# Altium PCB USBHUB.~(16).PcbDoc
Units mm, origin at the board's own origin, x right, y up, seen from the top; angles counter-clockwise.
Board outline 31.37 x 90.68 mm, 2 copper layers (Top Layer, Bottom Layer); 37 components, 26 nets, 182 pads, 0 vias.
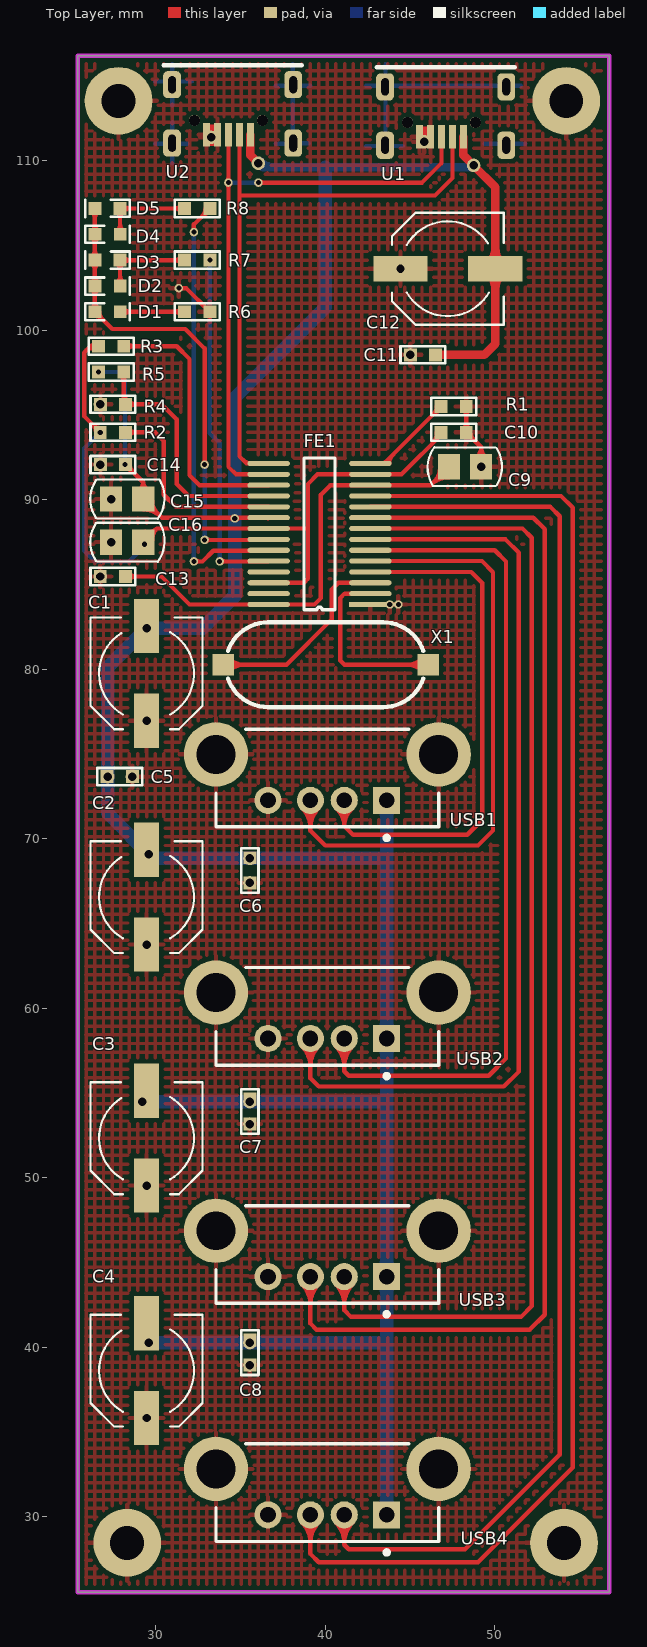
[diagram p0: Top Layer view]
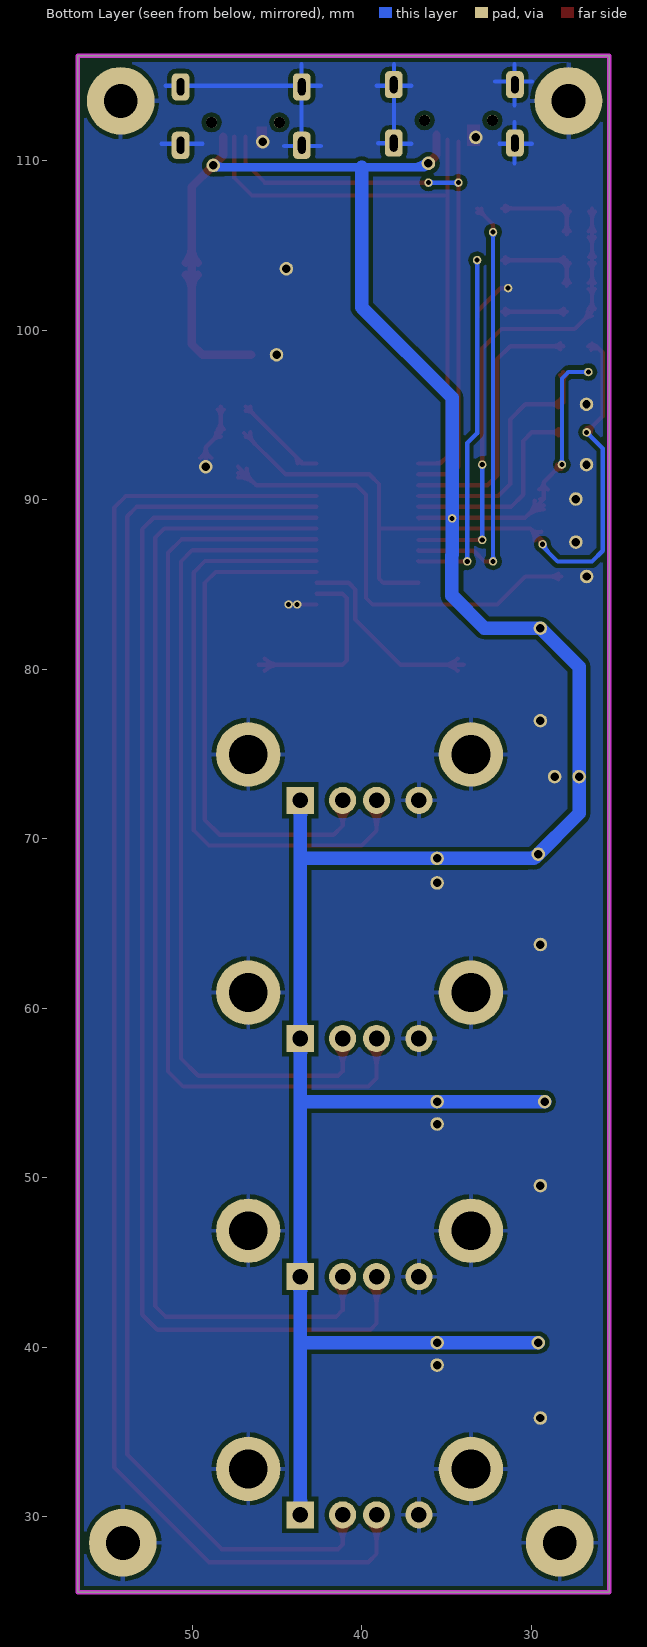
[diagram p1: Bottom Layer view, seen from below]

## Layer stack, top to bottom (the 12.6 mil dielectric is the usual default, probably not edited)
Top Layer: signal copper 0.0356
Dielectric: dielectric 0.32, FR-4, Dk 4.8
Bottom Layer: signal copper 0.0356

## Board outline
25.4,116.205 56.769,116.205 56.769,25.527 25.4,25.527 25.4,116.205

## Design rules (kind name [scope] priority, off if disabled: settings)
Clearance [All] p1: gap=0.254
PolygonConnect [All] p1: connectstyle=Relief reliefconductorwidth=0.254 reliefentries=4 polygonreliefangle="90 Angle"
RoutingVias [All] p1: holewidth=0.711 width=1.27 viastyle="Through Hole" minholewidth=0.711 minwidth=1.27 maxholewidth=0.711 maxwidth=1.27
SilkscreenOverComponentPads [All] p1: minsilkscreentomaskgap=0.254
SolderMaskExpansion [All] p1: expansion=0.102
TestPointUsage [All] p1: valid=0 allowmultiple=FALSE
Testpoint [All] p1: side=15 testpointundercomponent=TRUE minsize=1.016 maxsize=2.54 preferedsize=1.524 minholesize=0 maxholesize=1.016 preferedholesize=0.813 testpointgrid=0.025 style=1023 order=0123456789
Width [All] p1: maxlimit=2 minlimit=0.254 preferedwidth=0.254
23 further rules are at their usual default settings.

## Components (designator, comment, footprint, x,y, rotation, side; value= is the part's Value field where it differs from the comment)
C1 "Cap_Pol" cap_220uF/16V 29.464,79.756 r90 top
C2 "Cap_Pol" cap_220uF/16V 29.464,66.548 r90 top
C3 "Cap_Pol" cap_220uF/16V 29.464,52.324 r90 top
C4 "Cap_Pol" cap_220uF/16V 29.464,38.608 r90 top
C5 "Cap1" 0603 27.94,73.66 r180 top
C6 "Cap1" 0603 35.56,68.072 r90 top
C7 "Cap1" 0603 35.56,53.848 r90 top
C8 "Cap1" 0603 35.56,39.624 r90 top
C9 "Cap1" 2012[0805]-C 48.26,91.948 r180 top
C10 "Cap1" 0603 47.647,93.98 r180 top
C11 "Cap1" 0603 45.72,98.552 r0 top
C12 "Cap_Pol" cap_220uF/16V 47.244,103.632 r0 top
C13 "Cap1" 0603 27.534,85.471 r180 top
C14 "Cap1" 0603 27.429,92.075 r0 top
C15 "Cap1" 2012[0805]-C 28.321,90.043 r0 top
C16 "Cap1" 2012[0805]-C 28.321,87.503 r0 top
D1 "LED" 0603-Polar 27.111,101.092 r0 top
D2 "LED" 0603-Polar 27.111,102.616 r0 top
D3 "LED" 0603-Polar 27.216,104.14 r180 top
D4 "LED" 0603-Polar 27.111,105.664 r0 top
D5 "LED" 0603-Polar 27.216,107.188 r180 top
FE1 "FE1.1s" SSOP-28 42.672,83.82 r180 top
R1 "Res1" 0603 47.647,95.504 r180 top
R2 "Res1" 0603 27.534,93.98 r180 top
R3 "Res1" 0603 27.432,99.06 r180 top
R4 "Res1" 0603 27.429,95.631 r0 top
R5 "Res1" 0603 27.432,97.536 r180 top
R6 "Res1" 0603 32.512,101.092 r180 top
R7 "Res1" 0603 32.512,104.14 r180 top
R8 "Res1" 0603 32.512,107.188 r180 top
U1 "Micro-USB" MICRO-USB-F 47.117,113.665 r180 top
U2 "Micro-USB" MICRO-USB-F 34.544,113.792 r180 top
USB1 "USB" USB2.5-2V4A 40.132,76.454 r90 top
USB2 "USB" USB2.5-2V4A 40.132,62.399 r90 top
USB3 "USB" USB2.5-2V4A 40.132,48.345 r90 top
USB4 "USB" USB2.5-2V4A 40.132,34.29 r90 top
X1 "12M" XTAL_SMD 37.592,80.264 r0 top

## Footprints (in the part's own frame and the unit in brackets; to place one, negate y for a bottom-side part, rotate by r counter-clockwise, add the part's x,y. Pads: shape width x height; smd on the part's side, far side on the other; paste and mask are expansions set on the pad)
0603 [mil]
  rect 30x30 smd: 1(-27,0) 2(31.5,0)
  silkscreen extent -50,-20 54,20
0603-Polar [mil]
  rect 30x30 smd: 1(-27,0) 2(31.5,0)
  silkscreen extent -50,-20 54,20
2012[0805]-C [mm] "Chip Resistor; Body 2.0 x 1.3 mm (LxW typ)"
  rect 1.3x1.5 smd: 1(-0.95,0) 2(0.95,0)
  silkscreen extent -2.17,-1.16 2.21,1.14
cap_220uF/16V [mm]
  rect 3.2x1.5 smd: 1(-2.794,0) 2(2.8,0)
  silkscreen extent -3.3,-3.3 3.3,3.3
MICRO-USB-F [mm]
  rrect50% 1.05x1.6 hole 0.45 slot 1 at 90 deg: 0(-3.575,-0.7) 0(-3.575,2.75) 0(3.575,-0.7) 0(3.575,2.75)
  round 0.65 hole 0.65: 0(-1.75,1.4) 0(2.25,1.4)
  rect 0.4x1.4 smd: 1(-1.05,2.25) 2(-0.403,2.25) 3(0.246,2.25) 4(0.897,2.25) 5(1.546,2.25)
  silkscreen extent -4.08,-1.85 4.08,-1.85
SSOP-28 [mm]
  rect 2.5x0.3 smd: 1(0,0)
  oval 2.5x0.3 smd: 2(0,-0.64) 3(0,-1.28) 4(0,-1.92) 5(0,-2.56) 6(0,-3.2) 7(0,-3.84) 8(0,-4.48) 9(0,-5.12) 10(0,-5.76) 11(0,-6.4) 12(0,-7.04) 13(0,-7.68) 14(0,-8.32) 15(6,-8.32) 16(6,-7.68) 17(6,-7.04) 18(6,-6.4) 19(6,-5.76) 20(6,-5.12) 21(6,-4.48) 22(6,-3.84) 23(6,-3.2) 24(6,-2.56) 25(6,-1.92) 26(6,-1.28) 27(6,-0.64) 28(6,0)
  silkscreen extent 2.08,-8.64 3.92,0.32
USB2.5-2V4A [mm] "Connector; USB1.1, Type A, Thru-Hole; 4 Position; Vertical"
  rect 1.6x1.6 hole 0.92: 1(-4.19,-3.5)
  round 1.6 hole 0.92: 2(-4.19,-1) 3(-4.19,1) 4(-4.19,3.5)
  round 3.8 hole 2.3: 5(-1.48,6.57) 6(-1.48,-6.57)
  silkscreen extent -6.53,-6.57 0,6.57, body extent -5.76,-6.57 0,6.57, height 15
XTAL_SMD [mm]
  rect 1.27x1.27 smd: 1(-3.61,0) 2(8.49,0)
  silkscreen extent -3.33,-2.5 8.21,2.5

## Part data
C1 C2 C3 C4 C5 C6 C7 C8 C9 C10 C11 C12 C13 C14 C15 C16: "Capacitor"
D1 D2 D3 D4 D5: library part LED1, "Typical INFRARED GaAs LED"
R1 R2 R3 R4 R5 R6 R7 R8: "Resistor"
X1: library part XTAL_1, "Crystal Oscillator"

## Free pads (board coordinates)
  round 0.5 hole 0.3: 4(32.893,92.075) 7(32.258,105.791) 9(32.258,86.36) 10(32.893,87.63) 11(33.198,104.14) 12(33.782,86.36) 14(26.734,93.98) 15(29.337,87.376) 16(28.194,92.075) 17(26.632,97.536) 23(36.068,108.712) 24(34.298,108.712) 33(34.671,88.9) 54(31.369,102.489) 55(43.815,83.82) 56(44.323,83.82)
  round 0.8 hole 0.5: 21(36.068,109.855) 22(48.768,109.728) 25(29.464,82.423) 26(29.591,69.088) 27(29.21,54.483) 28(29.591,40.259) 29(27.178,73.66) 30(35.56,68.834) 31(35.56,54.483) 32(35.56,40.259) 38(33.274,111.379) 39(45.847,111.125) 40(26.743,95.631) 41(26.743,92.075) 42(27.371,90.043) 43(27.371,87.503) 44(26.734,85.471) 45(29.464,76.962) 46(29.464,63.754) 47(29.464,49.53) 48(29.464,35.814) 49(35.56,38.938) 50(35.56,53.162) 51(35.56,67.386) 52(28.626,73.66) 57(45.034,98.552) 58(44.45,103.632) 59(49.21,91.948)
  round 4 hole 2: 34(27.813,113.538) 35(54.229,113.538) 36(54.102,28.448) 37(28.321,28.448)

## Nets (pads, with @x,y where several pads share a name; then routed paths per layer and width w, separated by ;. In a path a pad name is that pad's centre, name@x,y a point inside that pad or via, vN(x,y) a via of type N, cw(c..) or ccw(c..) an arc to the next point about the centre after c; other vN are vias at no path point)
GND: C1.1 C2.1 C3.1 C4.1 C5.1 C6.1 C7.1 C8.1 C9.1 C10.1 C11.1 C12.1 C13.2 C14.1 C15.1 C16.1 FE1.1 pad.34 pad.35 pad.36 pad.37 pad.38 pad.39 pad.40 pad.41 pad.42 pad.43 pad.44 pad.45 pad.46 pad.47 pad.48 pad.49 pad.50 pad.51 pad.52 pad.54 pad.55 pad.56 pad.57 pad.58 pad.59 R1.1 R4.1 R6.1 U1.4 U1.5 U2.4 U2.5 USB1.4 USB1.5 USB1.6 USB2.4 USB2.5 USB2.6 USB3.4 USB3.5 USB3.6 USB4.4 USB4.5 USB4.6 | length 12.6
  Top Layer w0.254: pad.54 31.801,102.489 R6.1 R6.1@33.198,100.787 ; FE1.1 pad.55 pad.56 ; C10.1@48.153,94.16 ccw(c47.72,94.593) 48.333,94.593 ccw(c48.946,94.593) C10.1@48.512,94.16 ; R1.1@48.153,95.324 cw(c47.72,94.891) 48.333,94.891 cw(c48.946,94.891) R1.1@48.512,95.324 ; C10.1@48.333,93.726 cw(c48.333,93.113) 48.766,93.546 cw(c49.2,93.98) C10.1@48.587,93.98 ; R1.1 C10.1 49.21,93.103 ; C9.1@48.893,92.464 ccw(c48.408,93.103) 49.21,93.103 ; C9.1 49.21,93.103 ; C9.1@49.527,92.464 cw(c50.012,93.103) 49.21,93.103
NetD1_1: D1.1 D2.1 D3.2 D4.1 D5.2 FE1.22 pad.4 pad.10 | length 39
  Top Layer w0.254: D3.2@26.236,103.96 cw(c25.803,103.527) 26.416,103.527 cw(c27.029,103.527) D3.2@26.596,103.96 ; D3.2@26.236,104.32 ccw(c25.803,104.753) 26.416,104.753 ccw(c27.029,104.753) D3.2@26.596,104.32 ; D5.2@26.236,107.008 cw(c25.803,106.575) 26.416,106.575 cw(c27.029,106.575) D5.2@26.596,107.008 ; D1.1@26.246,101.272 ccw(c25.834,101.683) 26.416,101.683 ; D2.1@26.246,102.436 cw(c25.834,102.025) 26.416,102.025 ; D2.1@26.246,102.796 ccw(c25.834,103.207) 26.416,103.207 ; D4.1@26.246,105.484 cw(c25.834,105.073) 26.416,105.073 ; D4.1@26.246,105.844 ccw(c25.834,106.255) 26.416,106.255 ; 26.416,101.727 ccw(c27.061,101.727) D1.1@26.605,101.272 ; 26.416,101.981 cw(c27.061,101.981) D2.1@26.605,102.436 ; 26.416,103.251 ccw(c27.061,103.251) D2.1@26.605,102.796 ; 26.416,105.029 cw(c27.061,105.029) D4.1@26.605,105.484 ; 26.416,106.299 ccw(c27.061,106.299) D4.1@26.605,105.844 ; D5.2 D3.2 26.416,101.101 D1.1 27.441,100.076 31.75,100.076 32.893,98.933 pad.4 ; D1.1@26.425,100.838 cw(c26.425,100.225) 26.859,100.658 cw(c27.292,101.092) D1.1@26.679,101.092 ; pad.4@32.806,92.162 ccw(c32.596,92.372) 32.893,92.372 ccw(c33.19,92.372) pad.4@32.98,92.162 ; pad.10 FE1.22@36.642,87.63 ; pad.10@32.98,87.543 cw(c33.19,87.333) 33.19,87.63 cw(c33.19,87.927) pad.10@32.98,87.717
  Bottom Layer w0.254: pad.10@32.806,87.717 ccw(c32.596,87.927) 32.893,87.927 ccw(c33.19,87.927) pad.10@32.98,87.717 ; pad.4@32.806,91.988 cw(c32.596,91.778) 32.893,91.778 cw(c33.19,91.778) pad.4@32.98,91.988 ; pad.10 pad.4
NetD1_2: D1.2 R6.2 | length 5.7
  Top Layer w0.254: D1.2 R6.2 ; D1.2@28.091,100.912 cw(c28.524,100.479) 28.524,101.092 cw(c28.524,101.705) D1.2@28.091,101.272 ; R6.2@31.532,100.912 ccw(c31.099,100.479) 31.099,101.092 ccw(c31.099,101.705) R6.2@31.532,101.272
NetD2_2: D2.2 D3.1 R7.2 | length 9.2
  Top Layer w0.254: D3.1@27.722,103.96 cw(c27.289,103.527) 27.902,103.527 cw(c28.515,103.527) 28.081,103.96 cw(c28.515,103.527) 28.515,104.14 cw(c28.515,104.753) D3.1@28.081,104.32 ; D2.2@27.731,102.796 ccw(c27.32,103.207) 27.902,103.207 ; D2.2@27.902,102.625 D3.1 R7.2 ; 27.902,103.251 ccw(c28.546,103.251) D2.2@28.091,102.796 ; R7.2@31.532,103.96 ccw(c31.099,103.527) 31.099,104.14 ccw(c31.099,104.753) R7.2@31.532,104.32
NetD4_2: D4.2 D5.1 R8.2 | length 9.2
  Top Layer w0.254: D5.1@27.722,107.008 cw(c27.289,106.575) 27.902,106.575 cw(c28.515,106.575) 28.081,107.008 cw(c28.515,106.575) 28.515,107.188 cw(c28.515,107.801) D5.1@28.081,107.368 ; D4.2@27.731,105.844 ccw(c27.32,106.255) 27.902,106.255 ; D4.2@27.902,105.673 D5.1 R8.2 ; 27.902,106.299 ccw(c28.546,106.299) D4.2@28.091,105.844 ; R8.2@31.532,107.008 ccw(c31.099,106.575) 31.099,107.188 ccw(c31.099,107.801) R8.2@31.532,107.368
NetFE1_2: FE1.2 X1.2 | length 12.8
  Top Layer w0.254: FE1.2 41.153,84.46 40.894,84.201 40.894,80.518 41.148,80.264 X1.2 ; X1.2@45.723,79.905 ccw(c44.856,79.038) 44.856,80.264 ccw(c44.856,81.49) X1.2@45.723,80.623
NetFE1_3: FE1.3 X1.1 | length 13.7
  Top Layer w0.254: X1.1 37.719,80.264 40.386,82.931 40.386,84.709 40.777,85.1 FE1.3 ; X1.1@34.341,79.905 cw(c35.208,79.038) 35.208,80.264 cw(c35.208,81.49) X1.1@34.341,80.623
NetFE1_4: FE1.4 USB1.2 | length 34.8
  Top Layer w0.254: USB1.2@40.682,71.763 cw(c39.777,70.755) 41.132,70.755 ; USB1.2@40.852,71.952 cw(c40.288,71.325) 41.132,71.325 cw(c41.976,71.325) USB1.2@41.412,71.952 ; USB1.2 41.132,70.755 ; USB1.2@41.582,71.763 ccw(c42.487,70.755) 41.132,70.755 ; FE1.4 48.626,85.74 49.276,85.09 49.276,71.12 48.387,70.231 41.656,70.231 41.132,70.755
NetFE1_5: FE1.5 USB1.3 | length 40.2
  Top Layer w0.254: USB1.3@38.656,71.788 cw(c37.507,70.639) 39.132,70.639 cw(c40.757,70.639) USB1.3@39.608,71.788 ; USB1.3@38.836,71.968 cw(c38.12,71.252) 39.132,71.252 cw(c40.144,71.252) USB1.3@39.428,71.968 ; USB1.3 39.132,70.469 40.005,69.596 49.022,69.596 49.911,70.485 49.911,85.725 49.256,86.38 FE1.5
NetFE1_6: FE1.6 USB2.2 | length 53.8
  Top Layer w0.254: USB2.2@40.656,57.733 cw(c39.507,56.585) 41.132,56.585 cw(c42.757,56.585) USB2.2@41.608,57.733 ; USB2.2@40.836,57.913 cw(c40.12,57.198) 41.132,57.198 cw(c42.144,57.198) USB2.2@41.428,57.913 ; USB2.2 41.132,56.277 41.402,56.007 49.657,56.007 50.673,57.023 50.673,86.36 50.013,87.02 FE1.6
NetFE1_7: FE1.7 USB2.3 | length 59.1
  Top Layer w0.254: USB2.3@38.656,57.733 cw(c37.507,56.585) 39.132,56.585 cw(c40.757,56.585) USB2.3@39.608,57.733 ; USB2.3@38.836,57.913 cw(c38.12,57.198) 39.132,57.198 cw(c40.144,57.198) USB2.3@39.428,57.913 ; USB2.3 39.132,55.864 39.624,55.372 50.546,55.372 51.435,56.261 51.435,86.868 50.643,87.66 FE1.7
NetFE1_8: FE1.8 USB3.2 | length 72.7
  Top Layer w0.254: USB3.2@40.656,43.679 cw(c39.507,42.53) 41.132,42.53 cw(c42.757,42.53) USB3.2@41.608,43.679 ; USB3.2@40.836,43.858 cw(c40.12,43.143) 41.132,43.143 cw(c42.144,43.143) USB3.2@41.428,43.858 ; USB3.2 41.132,42.18 41.529,41.783 51.562,41.783 52.197,42.418 52.197,87.757 51.654,88.3 FE1.8
NetFE1_9: FE1.9 USB3.3 | length 78.2
  Top Layer w0.254: USB3.3@38.656,43.679 cw(c37.507,42.53) 39.132,42.53 cw(c40.757,42.53) USB3.3@39.608,43.679 ; USB3.3@38.836,43.858 cw(c38.12,43.143) 39.132,43.143 cw(c40.144,43.143) USB3.3@39.428,43.858 ; USB3.3 39.132,41.386 39.497,41.021 52.07,41.021 52.959,41.91 52.959,88.265 52.284,88.94 FE1.9
NetFE1_10: FE1.10 USB4.2 | length 87.8
  Top Layer w0.254: USB4.2@40.656,29.624 cw(c39.507,28.475) 41.132,28.475 cw(c42.757,28.475) USB4.2@41.608,29.624 ; USB4.2@40.836,29.804 cw(c40.12,29.088) 41.132,29.088 cw(c42.144,29.088) USB4.2@41.428,29.804 ; USB4.2 41.132,28.337 41.402,28.067 48.26,28.067 53.848,33.655 53.848,89.027 53.295,89.58 FE1.10
NetFE1_11: FE1.11 USB4.3 | length 93.3
  Top Layer w0.254: USB4.3@38.656,29.624 cw(c37.507,28.475) 39.132,28.475 cw(c40.757,28.475) USB4.3@39.608,29.624 ; USB4.3@38.836,29.804 cw(c38.12,29.088) 39.132,29.088 cw(c40.144,29.088) USB4.3@39.428,29.804 ; USB4.3 39.132,27.797 39.624,27.305 49.022,27.305 54.61,32.893 54.61,89.535 53.925,90.22 FE1.11
NetFE1_14: FE1.14 R1.2 | length 7.2
  Top Layer w0.254: FE1.14 43.483,92.14 R1.2 ; FE1.14@43.541,92.14 cw(c43.681,92.14) FE1.14@43.582,92.239 ; FE1.14@43.795,92.14 cw(c44.548,92.14) 44.016,92.673 ; R1.2@46.593,95.504 cw(c45.98,95.504) 46.413,95.07 cw(c46.847,94.637) R1.2@46.847,95.25
NetFE1_15: FE1.15 U1.2 U2.2 | length 36.5
  Top Layer w0.254: U2.2@34.947,111.252 34.947,107.95 ; 35.184,92.324 ccw(c35.572,92.711) FE1.15@35.572,92.163 ; FE1.15 35.368,92.14 34.947,92.561 34.947,107.95 ; U1.2 47.52,108.988 46.482,107.95 34.947,107.95
NetFE1_16: FE1.16 pad.23 pad.24 U1.3 U2.3 | length 38.7
  Top Layer w0.254: pad.24@34.211,108.625 cw(c34.001,108.415) 34.298,108.415 cw(c34.594,108.415) pad.24@34.384,108.625 ; pad.24@34.211,108.799 ccw(c34.001,109.009) 34.298,109.009 ccw(c34.594,109.009) pad.24@34.384,108.799 ; U2.3@34.298,111.125 34.298,91.94 34.738,91.5 FE1.16 ; pad.23 45.72,108.712 46.871,109.863 U1.3 ; pad.23@36.155,108.625 cw(c36.365,108.415) 36.365,108.712 cw(c36.365,109.009) pad.23@36.155,108.799
  Bottom Layer w0.254: pad.24 pad.23 ; pad.24@34.384,108.625 cw(c34.594,108.415) 34.594,108.712 cw(c34.594,109.009) pad.24@34.384,108.799 ; pad.23@35.981,108.625 ccw(c35.771,108.415) 35.771,108.712 ccw(c35.771,109.009) pad.23@35.981,108.799
NetFE1_17: FE1.17 R3.1 | length 16.9
  Top Layer w0.254: R3.1 31.242,99.06 32.004,98.298 32.004,91.44 32.584,90.86 FE1.17 ; R3.1@28.297,98.88 cw(c28.731,98.447) 28.731,99.06 cw(c28.731,99.673) R3.1@28.297,99.24
NetFE1_18: FE1.18 R4.2 R5.1 | length 17.3
  Top Layer w0.254: R5.1@27.938,97.356 cw(c27.505,96.923) 28.118,96.923 cw(c28.731,96.923) R5.1@28.297,97.356 ; R5.1 28.118,96.266 ; R4.2@28.357,95.851 cw(c28.599,96.266) 28.118,96.266 ; R4.2@28.408,95.451 cw(c28.842,95.018) 28.842,95.631 cw(c28.842,96.244) R4.2@28.408,95.811 ; FE1.18 31.954,90.22 31.242,90.932 31.242,94.742 30.353,95.631 R4.2 28.118,95.742 28.118,96.266
NetFE1_19: FE1.19 R2.1 | length 13.1
  Top Layer w0.254: R2.1 29.972,93.98 30.48,93.472 30.48,90.297 31.197,89.58 FE1.19 ; R2.1@28.399,93.8 cw(c28.833,93.367) 28.833,93.98 cw(c28.833,94.593) R2.1@28.399,94.16
NetFE1_23: FE1.23 pad.7 pad.9 R8.1 | length 28.7
  Top Layer w0.254: pad.7@32.171,105.878 ccw(c31.961,106.088) 32.258,106.088 ccw(c32.555,106.088) pad.7@32.345,105.878 ; pad.9 32.766,86.36 33.401,86.995 36.647,86.995 FE1.23 ; pad.7 32.258,106.248 R8.1 ; pad.9@32.345,86.273 cw(c32.555,86.063) 32.555,86.36 cw(c32.555,86.657) pad.9@32.345,86.447 ; R8.1@32.944,107.188 cw(c32.331,107.188) 32.764,106.754 cw(c33.198,106.321) R8.1@33.198,106.934
  Bottom Layer w0.254: pad.9@32.171,86.447 ccw(c31.961,86.657) 32.258,86.657 ccw(c32.555,86.657) pad.9@32.345,86.447 ; pad.7@32.171,105.704 cw(c31.961,105.494) 32.258,105.494 cw(c32.555,105.494) pad.7@32.345,105.704 ; pad.9 pad.7
NetFE1_24: FE1.24 pad.11 pad.12 R7.1 | length 22.3
  Top Layer w0.254: pad.12 36.652,86.36 FE1.24 ; pad.12@33.869,86.273 cw(c34.079,86.063) 34.079,86.36 cw(c34.079,86.657) pad.12@33.869,86.447
  Bottom Layer w0.254: pad.11@33.111,104.053 cw(c32.901,103.843) 33.198,103.843 cw(c33.495,103.843) pad.11@33.285,104.053 ; pad.11 33.198,93.929 33.782,93.345 pad.12 ; pad.12@33.695,86.447 ccw(c33.485,86.657) 33.782,86.657 ccw(c34.079,86.657) pad.12@33.869,86.447
VCC1_8: C9.2 C13.1 FE1.12 FE1.28 | length 30.4
  Top Layer w0.254: C13.1 30.353,85.471 32.004,83.82 FE1.28 39.37,83.82 39.751,84.201 39.751,90.297 40.314,90.86 FE1.12 46.222,90.86 C9.2 ; C13.1@28.399,85.291 cw(c28.833,84.858) 28.833,85.471 cw(c28.833,86.084) C13.1@28.399,85.651 ; 46.246,90.884 cw(c47.31,89.821) C9.2@47.31,91.325 ; 46.488,91.126 ccw(c45.766,91.848) C9.2@46.787,91.848 ; C9.2@46.68,91.318 cw(c47.31,90.688) C9.2@47.31,91.579
VCC3_3: C10.2 C16.2 FE1.13 FE1.21 FE1.26 pad.14 pad.15 R2.2 R3.2 | length 53
  Top Layer w0.254: 25.915,98.813 cw(c26.527,98.2) R3.2 ; 25.927,98.825 cw(c26.221,98.531) R3.2@26.476,98.859 ; 26.131,99.029 cw(c26.399,98.76) R3.2 ; R3.2@26.42,98.921 ccw(c26.162,98.752) 26.162,99.06 ; R3.2@26.42,99.199 cw(c26.162,99.368) 26.162,99.06 ; R2.2@26.48,93.98 ccw(c25.867,93.98) 26.3,94.414 ccw(c26.734,94.847) R2.2@26.734,94.234 ; R2.2@26.611,93.98 ccw(c26.314,93.98) 26.524,94.19 ccw(c26.734,94.4) R2.2@26.734,94.103 ; R2.2 25.781,94.933 25.781,98.679 26.162,99.06 ; C16.2 30.068,88.3 ; C16.2@29.395,88.111 ccw(c29.563,88.805) 30.068,88.3 ; C16.2@29.46,87.376 cw(c30.223,87.376) C16.2@29.683,87.915 ; C16.2@29.794,87.615 cw(c30.73,87.638) 30.068,88.3 ; FE1.26 38.745,85.1 38.989,85.344 38.989,90.932 39.557,91.5 FE1.13 44.51,91.5 C10.2@46.952,93.942 ; 38.954,88.3 FE1.21 30.068,88.3 ; 46.312,93.302 ccw(c45.635,93.98) C10.2@46.593,93.98 ; C10.2@46.658,93.648 cw(c46.847,93.458) C10.2@46.847,93.726 ; 26.162,99.06 R3.2
  Bottom Layer w0.254: pad.14@26.611,93.98 cw(c26.314,93.98) 26.524,93.77 cw(c26.734,93.56) pad.14@26.734,93.857 ; pad.14 25.781,93.027 25.781,86.995 26.416,86.36 28.448,86.36 29.337,87.249 pad.15 ; 29.037,86.949 ccw(c28.61,87.376) pad.15@29.214,87.376
VCC5: C1.2 C2.2 C3.2 C4.2 C5.2 C6.2 C7.2 C8.2 C11.2 C12.2 C14.2 C15.2 FE1.20 pad.16 pad.17 pad.21 pad.22 pad.25 pad.26 pad.27 pad.28 pad.29 pad.30 pad.31 pad.32 pad.33 R5.2 U1.1 U2.1 USB1.1 USB2.1 USB3.1 USB4.1 | length 204
  Top Layer w0.254: C14.2@28.194,91.952 cw(c28.194,91.571) C14.2@28.464,91.84 ; C14.2@28.229,91.821 cw(c28.229,91.208) 28.662,91.641 cw(c29.096,92.075) C14.2@28.483,92.075 ; C14.2 29.271,91.033 ; C15.2@29.017,90.6 ccw(c28.775,91.033) 29.271,91.033 ; C15.2@29.271,89.42 cw(c29.271,87.916) 30.335,88.979 ; C15.2@29.271,89.674 cw(c29.271,88.783) C15.2@29.901,89.413 ; C15.2@29.464,90.043 C15.2 ; C15.2@29.525,90.6 cw(c29.767,91.033) 29.271,91.033 ; C15.2@29.794,89.943 ccw(c30.815,89.943) 30.093,89.221 ; 34.277,88.94 cw(c34.277,88.506) pad.33@34.584,88.813 ; pad.33@34.758,88.813 cw(c35.065,88.506) 35.065,88.94 ; FE1.20@36.632,88.9 FE1.20 30.374,88.94 C15.2 ; C15.2 29.271,91.033
  Top Layer w0.5: U2.1 35.594,110.329 pad.21 ; C11.2 49.403,98.552 50.044,99.193 C12.2 50.044,108.452 pad.22 48.167,110.329 U1.1 ; C12.2@49.69,103.278 cw(c48.837,102.425) 50.044,102.425 cw(c51.251,102.425) C12.2@50.398,103.278 ; C12.2@49.69,103.986 ccw(c48.837,104.839) 50.044,104.839 ccw(c51.251,104.839) C12.2@50.398,103.986
  Bottom Layer w0.254: pad.17 27.813,97.536 28.194,97.155 pad.16 ; pad.17@26.719,97.449 cw(c26.929,97.239) 26.929,97.536 cw(c26.929,97.833) pad.17@26.719,97.623 ; pad.16@28.107,92.162 ccw(c27.897,92.372) 28.194,92.372 ccw(c28.491,92.372) pad.16@28.281,92.162
  Bottom Layer w0.5: pad.21 36.312,109.611 40.005,109.611 48.651,109.611 pad.22 ; pad.21@36.174,109.961 ccw(c37.019,110.806) 37.019,109.611 ; 48.123,109.611 ccw(c48.123,110.373) pad.22@48.662,109.834
  Bottom Layer w0.8: pad.27 43.632,54.483 ; pad.28 43.632,40.259 ; pad.26 ccw(c30.204,69.701) 30.204,68.834 ; 40.005,109.611 40.005,101.346 34.671,96.012 34.671,86.749 34.686,86.734 34.686,84.343 32.766,82.423 pad.25 27.178,80.137 27.178,71.501 29.845,68.834 43.505,68.834 ; USB4.1@43.349,30.383 ccw(c42.666,31.066) 43.632,31.066 ccw(c44.598,31.066) USB4.1@43.915,30.383 ; USB3.1@43.349,43.872 cw(c42.666,43.189) 43.632,43.189 cw(c44.598,43.189) USB3.1@43.915,43.872 ; USB3.1@43.349,44.438 ccw(c42.666,45.12) 43.632,45.12 ccw(c44.598,45.12) USB3.1@43.915,44.438 ; USB2.1@43.349,57.926 cw(c42.666,57.244) 43.632,57.244 cw(c44.598,57.244) USB2.1@43.915,57.926 ; USB2.1@43.349,58.492 ccw(c42.666,59.175) 43.632,59.175 ccw(c44.598,59.175) USB2.1@43.915,58.492 ; USB1.1@43.349,71.981 cw(c42.666,71.298) 43.632,71.298 cw(c44.598,71.298) USB1.1@43.915,71.981 ; USB4.1 USB3.1 43.632,54.483 ; USB1.1 USB2.1 43.632,54.483
pads on no net: FE1.25 FE1.27 U1.0 U2.0
copper on no net: | length 36
  Bottom Layer w0.254: 29.972,110.998 31.877,110.998 ; 29.972,114.681 32.131,114.681 ; 30.988,109.855 30.988,112.268 ; 30.988,113.284 30.988,115.697 ; 37.084,110.998 38.075,110.998 38.1,111.023 ; 37.084,114.427 39.116,114.427 ; 38.1,115.697 38.1,114.492 38.1,111.023 ; 39.033,111.042 38.119,111.042 38.1,111.023 ; 42.418,110.871 44.577,110.871 ; 42.418,114.427 51.562,114.427 ; 43.561,110.934 43.561,115.697 ; 49.403,110.998 51.816,110.998

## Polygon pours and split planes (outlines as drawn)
GND on Top Layer "Bottom Layer-No Net" (hatched 90Degree grid 0.508 track 0.203): 25.4,116.205 56.769,116.205 56.769,25.527 25.4,25.527 25.4,116.205
GND on Bottom Layer "Bottom Layer-No Net" (solid): 25.4,116.205 56.769,116.205 56.769,25.527 25.4,25.527 25.4,116.205

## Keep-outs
Keep-Out Layer:
  the board outline again, w0.254

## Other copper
Top Layer:
  rectangle net GND: 45.593,110.744 46.228,112.014
  rectangle net GND: 33.02,110.871 33.782,112.141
